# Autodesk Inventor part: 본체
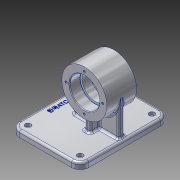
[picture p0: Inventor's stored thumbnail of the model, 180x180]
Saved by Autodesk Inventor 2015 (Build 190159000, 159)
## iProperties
Created: 2019-09
Part Number: 본체
Material: 알루미늄 6061
Document SubType Name: Modeling
Designer: Lineart
Density: 2.7 g/cm^3
Appearance: 알루미늄 - 평지
Mass: 554.62 g
Surface Area: 495.884 cm^2
Volume: 205.415 cm^3
Author: Lineart
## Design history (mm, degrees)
sketch "스케치1"
  geometry: L1 (-51, -49)-(51, -49); L2 (63, -37)-(63, 37); L3 (51, 49)-(-51, 49); L4 (-63, 37)-(-63, -37); L5 (-63, -49)-(63, 49); L6 (63, -49)-(-63, 49); A1 r 12 centre (-51, 37) between (-51, 49) and (-63, 37); A2 r 12 centre (51, 37) between (63, 37) and (51, 49); A3 r 12 centre (51, -37) between (51, -49) and (63, -37); A4 r 12 centre (-51, -37) between (-63, -37) and (-51, -49); 1 further point
  constraints: 12 end point, 8 point on circle, 8 point on line, 8 tangent, 4 centre point, 3 equal radius, 2 midpoint, 2 parallel, 1 horizontal, 1 perpendicular
  dimensions: "d0" = 126 distance of L6.end L5.end; "d1" = 98 distance of L5.end L6.start; "d2" = 12 radius of A1
extrude "돌출1" new body sketch "스케치1" distance "d3" = 9; taper "d4" = 0 deg
sketch "스케치2"
  geometry: A1 r 12 centre (-51, 37) between (-51, 49) and (-63, 37) reference; A2 r 12 centre (51, 37) between (63, 37) and (51, 49) reference; A3 r 12 centre (-51, -37) between (-63, -37) and (-51, -49) reference; A4 r 12 centre (51, -37) between (51, -49) and (63, -37) reference; 5 further points
  constraints: 4 coincident
hole "구멍1" sketch "스케치2" at (-51, 37), (51, 37), (-51, -37), (51, -37) diameter "d5" = 4.5; stored, may be unused: countersink angle "d9" = 90 deg, drill point angle "d11" = 0 deg; dims "d6" = 6, "d7" = 8, "d8" = 4.4, "d10" = 9
sketch "스케치3"
  geometry: L1 (-17, -9)-(17, -9); L2 (17, -9)-(17, -17); L3 (17, -17)-(-17, -17); L4 (-17, -17)-(-17, -9); L5 (17, -13)-(-17, -13); L6 (51, 49)-(-51, 49) reference; L7 (-4, 19)-(4, 19); L8 (4, 19)-(4, -45); L9 (4, -45)-(-4, -45); L10 (-4, -45)-(-4, 19); 5 further points
  constraints: 18 end point, 6 midpoint, 4 parallel, 2 horizontal, 2 perpendicular, 2 vertical alignment, 1 horizontal alignment
  dimensions: "d14" = 34 distance of L2.end L3.end; "d15" = 8 distance of L1.end L2.end; "d16" = 62 distance between parallel lines of L5 L6; "d19" = 8 distance of L8.end L9.end; "d20" = 64 distance of L7.end L8.end
extrude "돌출3" join sketch "스케치3" distance "d21" = 50; taper "d22" = 0 deg
sketch "스케치4"
  geometry: L1 (-9, 59)-(-17, 59) reference; L2 (-34.75, 0)-(-39.25, 0) reference; C1 r 32 at (-13, 59); 2 further points
  constraints: 1 centre point, 1 coincident, 1 midpoint
  dimensions: "d23" = 64 diameter of C1; "d24" = 59 distance from line of L2 C1.centre
extrude "돌출4" join sketch "스케치4" stored distance "d25" = 42; taper "d26" = 0 deg
sketch "스케치5"
  geometry: C1 r 32 at (0, 0) reference; C2 r 21 at (0, 0); 1 further point
  constraints: 1 centre point, 1 coincident
  dimensions: "d27" = 42 diameter of C2
extrude "돌출5" cut sketch "스케치5" distance "d28" = 15; taper "d29" = 0 deg
sketch "스케치6"
  geometry: C1 r 21 at (0, 0) reference; C2 r 18 at (0, 0); 1 further point
  constraints: 1 centre point, 1 coincident
  dimensions: "d30" = 36 diameter of C2
extrude "돌출6" cut sketch "스케치6" distance "d31" = 12; taper "d32" = 0 deg
sketch "스케치7"
  geometry: C1 r 32 at (0, 0) reference; C2 r 21 at (0, 0); 1 further point
  constraints: 1 centre point, 1 coincident
  dimensions: "d33" = 42 diameter of C2
extrude "돌출7" cut sketch "스케치7" distance "d34" = 15; taper "d35" = 0 deg
sketch "스케치8"
  geometry: C1 r 21 at (0, 0) reference; 2 further points
  constraints: 1 horizontal alignment
  dimensions: "d36" = 26 distance of C1.centre point (-26, 0)
hole "구멍2" sketch "스케치8" at (-26, 0) diameter "d37" = 3.242; stored, may be unused: countersink angle "d41" = 90 deg, drill point angle "d43" = 118 deg; dims "d38" = 8, "d39" = 8, "d40" = 4.4, "d42" = 10
fillet "모깎기1" dims "d47" = 3
fillet "모깎기2" dims "d48" = 3
fillet "모깎기3" dims "d49" = 3
chamfer "모따기1" distance "d50" = 1; stored, may be unused: second distance "d51" = 2, angle "d52" = 45 deg
sketch "스케치9"
  geometry: L1 (51, 49)-(-51, 49) reference; L2 (63, -37)-(63, 37) reference; 2 further points
  constraints: 1 other
  dimensions: "d53" = 10 distance from line of point (0, 39) L1; "d54" = 63 distance from line of L2 point (0, 39)
feature "엠보싱1" sketch "스케치9" dims "d55" = 0.5, "d56" = 0
fillet "모깎기4" dims "d57" = 0.3
node "솔리드1"
pattern_circular "원형 패턴1" dims angle "d45" = 360 deg
mirror "대칭1"
